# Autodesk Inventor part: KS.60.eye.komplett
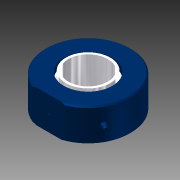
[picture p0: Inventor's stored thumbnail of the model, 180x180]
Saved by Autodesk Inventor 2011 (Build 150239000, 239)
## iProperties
Created: 2010-11
Part Number: KS.60.eye.komplett
Document SubType Name: Modeling
Designer: tribel
Density: 1 g/cm^3
Author: tribel
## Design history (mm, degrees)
derived "KS60eye.iam"
body "Solid1"
node "Lagerhus60.ipt:1"
node "Kule60HO.ipt:1"
sketch "Smørenippel.ipt:1"
